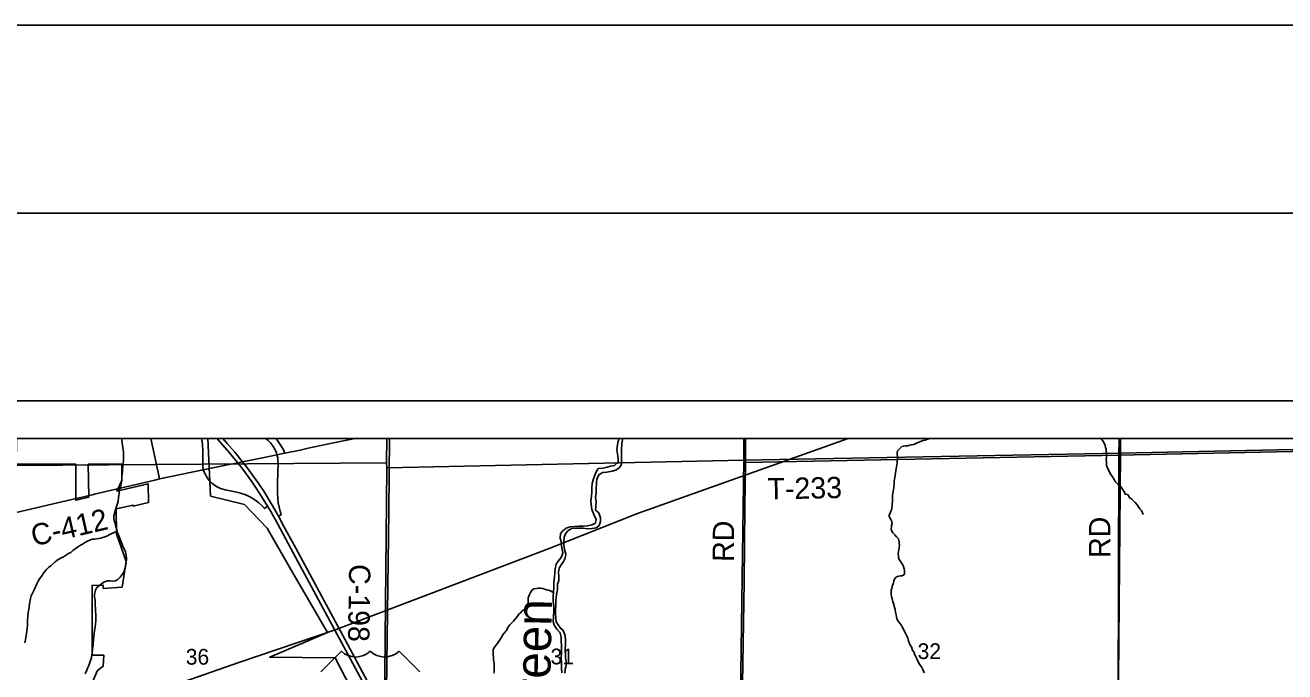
# Model space of a CAD drawing. Extents: x 0 to 34, y 0 to 22.
# Drawn here: x 25.144 to 28.499, y 20.279 to 22 of the extents above; entities that cross this region are included whole.
import ezdxf

# ---------------------------------------------------------------- set-up
doc = ezdxf.new("R2010")
doc.units = 0
for name, color, linetype in [('GM_X_City_Street', 7, 'Continuous'), ('GM_X_County_Road', 7, 'Continuous'), ('GM_X_County_Road_Text', 7, 'Continuous'), ('GM_X_Interchange_Ramps', 7, 'Continuous'), ('GM_X_Minor_River', 7, 'Continuous'), ('GM_X_Minor_River_Text', 7, 'Continuous'), ('GM_X_Rail_Line', 7, 'Continuous'), ('GM_X_Section', 7, 'Continuous'), ('GM_X_Section_Text', 7, 'Continuous'), ('GM_X_State_Route', 7, 'Continuous'), ('GM_X_Township_Road', 7, 'Continuous'), ('GM_X_Township_Road_Text', 7, 'Continuous'), ('GM_X_US_Route', 7, 'Continuous'), ('GM_X_US_Shield', 7, 'Continuous'), ('SH_Border', 7, 'Continuous'), ('SH_Cut_Line', 7, 'Continuous'), ('SH_Data', 7, 'Continuous')]:
    doc.layers.add(name, color=color, linetype=linetype)

msp = doc.modelspace()

# ---------------------------------------------------------------- linework, layer by layer
at = {"layer": 'GM_X_City_Street'}
for points in [[(26.0952, 20.0736), (25.9699, 20.3158), (25.7956, 20.3177), (25.9492, 20.3836), (25.8479, 20.5576), (25.7889, 20.661), (25.7281, 20.7242), (25.638, 20.7466), (25.6303, 20.9), (25.1147, 20.9)], [(25.5023, 20.7921), (25.4882, 20.8587), (25.4785, 20.9)], [(25.113, 20.8313), (25.279, 20.8313), (25.2789, 20.7356), (25.3135, 20.7434), (25.3119, 20.8313), (25.4015, 20.8314), (25.4014, 20.7881), (25.3884, 20.7601), (25.4717, 20.7796), (25.4728, 20.7296), (25.4315, 20.7201), (25.4315, 20.7227), (25.3866, 20.7123), (25.3878, 20.646), (25.4131, 20.5726), (25.4023, 20.5042), (25.3522, 20.5007), (25.3522, 20.5093), (25.3225, 20.5087), (25.3225, 20.3236), (25.3537, 20.3233), (25.3521, 20.2935), (25.3368, 20.282), (25.3235, 20.252)]]:
    msp.add_lwpolyline(points, dxfattribs=at)
at = {"layer": 'GM_X_County_Road'}
for points in [[(26.1076, 20.2958), (26.1077, 20.3027), (26.1124, 20.7064), (26.1147, 20.9)], [(25.4897, 20.7892), (25.5023, 20.7921), (25.6186, 20.8161)], [(25.3323, 20.7524), (25.3905, 20.766), (25.4013, 20.7686)], [(25.4013, 20.7686), (25.478, 20.7865), (25.4897, 20.7892)], [(24.9673, 20.6671), (25.2835, 20.741), (25.2924, 20.7431)], [(25.2924, 20.7431), (25.3224, 20.7501), (25.3323, 20.7524)], [(26.301, 19.8288), (26.3002, 19.8371), (26.2987, 19.8445), (26.2969, 19.8503), (26.2927, 19.8612), (26.2875, 19.8718), (26.2782, 19.8896), (26.2651, 19.9141), (26.25, 19.9419), (26.2307, 19.9774), (26.2049, 20.0253), (26.1749, 20.0809), (26.146, 20.1344), (26.121, 20.1805), (26.1119, 20.1994), (26.1076, 20.2154), (26.1067, 20.2326), (26.1076, 20.2958)]]:
    msp.add_lwpolyline(points, dxfattribs=at)
at = {"layer": 'GM_X_Interchange_Ramps'}
for points in [[(25.8143, 20.8561), (25.8132, 20.8617), (25.8087, 20.8714), (25.803, 20.8809), (25.7978, 20.8881), (25.7918, 20.8945), (25.7851, 20.9)], [(25.819, 20.693), (25.8264, 20.697), (25.8235, 20.7068), (25.8207, 20.717), (25.8182, 20.7287), (25.8168, 20.7397), (25.8161, 20.7553), (25.8165, 20.7789), (25.8173, 20.8124), (25.8176, 20.8303), (25.8175, 20.8426), (25.8167, 20.8485), (25.8143, 20.8561)], [(25.6186, 20.8161), (25.6204, 20.8122), (25.6243, 20.8039), (25.6288, 20.7956), (25.6345, 20.7878), (25.6359, 20.7863)], [(25.6359, 20.7863), (25.6409, 20.7812), (25.648, 20.7753), (25.6557, 20.7708), (25.6642, 20.767), (25.6769, 20.7636), (25.7032, 20.7578), (25.7178, 20.7543), (25.729, 20.7506), (25.7392, 20.7462), (25.7503, 20.7401), (25.7594, 20.734), (25.7667, 20.7285), (25.7742, 20.7216), (25.7814, 20.714), (25.7899, 20.7195)]]:
    msp.add_lwpolyline(points, dxfattribs=at)
at = {"layer": 'GM_X_Minor_River'}
for points in [[(25.4008, 20.9), (25.4014, 20.8945), (25.4021, 20.8888), (25.4036, 20.882), (25.4046, 20.8744), (25.4057, 20.8653), (25.4064, 20.8596), (25.4063, 20.8516), (25.4058, 20.8417), (25.4053, 20.836), (25.4041, 20.8258), (25.4032, 20.8175), (25.4032, 20.8122), (25.4023, 20.8042), (25.4019, 20.7989), (25.4014, 20.7928), (25.401, 20.7856), (25.3993, 20.7754), (25.3981, 20.7693), (25.3958, 20.7633), (25.3945, 20.7549), (25.3937, 20.7485), (25.3929, 20.7432)], [(26.6316, 20.6613), (26.641, 20.6596), (26.6543, 20.6607), (26.6646, 20.6623), (26.6731, 20.6685), (26.6764, 20.6791), (26.6767, 20.6886), (26.6717, 20.7016), (26.6636, 20.7094), (26.6643, 20.7193), (26.665, 20.7329), (26.663, 20.7432), (26.6645, 20.7557), (26.6651, 20.766), (26.6659, 20.7815), (26.667, 20.7925), (26.673, 20.8041), (26.6823, 20.8095), (26.6933, 20.8104), (26.7078, 20.813), (26.7169, 20.8158), (26.7266, 20.822), (26.7321, 20.8306), (26.732, 20.842), (26.7328, 20.8575), (26.7328, 20.8693), (26.7332, 20.886), (26.7354, 20.8969), (26.7363, 20.9)], [(26.7261, 20.9), (26.7239, 20.8931), (26.7214, 20.8829), (26.7199, 20.87), (26.7219, 20.8593), (26.7231, 20.8464), (26.7232, 20.8365), (26.7142, 20.8277), (26.7032, 20.8264), (26.694, 20.8237), (26.6826, 20.8213), (26.6704, 20.8197), (26.6652, 20.8112), (26.6616, 20.8021), (26.6567, 20.7901), (26.6545, 20.7799), (26.6531, 20.7693), (26.6536, 20.7579), (26.6521, 20.7462), (26.651, 20.7341), (26.6515, 20.7246), (26.653, 20.7112), (26.6566, 20.7024)], [(27.5537, 20.9), (27.5509, 20.8992), (27.5455, 20.8969), (27.541, 20.8955), (27.536, 20.8944), (27.5284, 20.8918), (27.52, 20.8881), (27.5109, 20.884), (27.5048, 20.8826), (27.4991, 20.8819), (27.4949, 20.8808), (27.4892, 20.8801), (27.4843, 20.8798), (27.4793, 20.8783), (27.4736, 20.8734), (27.4678, 20.8667)], [(28.0092, 20.9), (28.0099, 20.8992), (28.014, 20.8934), (28.017, 20.8892), (28.0203, 20.8812), (28.0217, 20.8759), (28.0228, 20.8713), (28.0235, 20.8671), (28.0242, 20.8618), (28.0241, 20.8508), (28.0236, 20.8432), (28.024, 20.8383), (28.0239, 20.833), (28.0242, 20.8284), (28.0272, 20.8216), (28.0298, 20.8158), (28.032, 20.8109), (28.0346, 20.8048), (28.0406, 20.7967), (28.0435, 20.7914), (28.0484, 20.7849), (28.0544, 20.778), (28.0604, 20.7741), (28.0653, 20.768), (28.0724, 20.7569), (28.0738, 20.7516), (28.0799, 20.7504), (28.0836, 20.7462), (28.0858, 20.742), (28.0904, 20.7396), (28.096, 20.7343), (28.1005, 20.7293), (28.1065, 20.722), (28.1106, 20.7166), (28.1139, 20.7121), (28.1169, 20.7078), (28.1214, 20.6979)], [(27.4678, 20.8667), (27.4666, 20.8621), (27.4669, 20.8576), (27.4676, 20.853), (27.4672, 20.8454), (27.4667, 20.8397), (27.4663, 20.8352), (27.4647, 20.8246), (27.4642, 20.8189), (27.4634, 20.8147), (27.4618, 20.8075), (27.461, 20.8018), (27.4597, 20.792), (27.4585, 20.7851), (27.4588, 20.7768), (27.458, 20.7719), (27.4576, 20.7677), (27.4563, 20.7609), (27.4551, 20.7548), (27.4543, 20.7491), (27.4539, 20.7419), (27.4538, 20.7336), (27.4533, 20.7241), (27.4528, 20.7157), (27.452, 20.7116), (27.45, 20.7063), (27.4477, 20.7014), (27.445, 20.6965), (27.4449, 20.6923), (27.4487, 20.6858), (27.452, 20.6793), (27.4531, 20.6736), (27.4519, 20.6687), (27.4515, 20.6645), (27.451, 20.6596), (27.4517, 20.6554), (27.4547, 20.6485), (27.4607, 20.6435), (27.4652, 20.6385), (27.4701, 20.6324), (27.4715, 20.6259), (27.4722, 20.6202), (27.4725, 20.6161), (27.4717, 20.6089), (27.4709, 20.6043), (27.4701, 20.599), (27.4696, 20.5926), (27.4699, 20.5865), (27.4702, 20.5815), (27.4747, 20.5743), (27.4784, 20.5689), (27.4825, 20.5617), (27.4855, 20.5529), (27.4865, 20.5476), (27.4865, 20.5434), (27.4861, 20.5385), (27.4796, 20.5347), (27.4754, 20.534), (27.4712, 20.5337), (27.4666, 20.5326), (27.4624, 20.5292), (27.4597, 20.5251), (27.4578, 20.5209), (27.4566, 20.516), (27.4531, 20.5062), (27.4523, 20.5016), (27.4503, 20.4963), (27.4505, 20.4846), (27.4516, 20.4789), (27.4531, 20.4728), (27.4553, 20.4659), (27.4567, 20.461), (27.4585, 20.4545), (27.4596, 20.4499), (27.4611, 20.445), (27.4625, 20.4374), (27.464, 20.4305), (27.465, 20.4252), (27.4661, 20.4206), (27.4683, 20.4149), (27.4724, 20.4096), (27.4769, 20.4042), (27.4803, 20.3985), (27.484, 20.3908), (27.4862, 20.3862), (27.4888, 20.382), (27.4914, 20.3763), (27.4947, 20.3687), (27.4962, 20.3645), (27.498, 20.3584), (27.4999, 20.3519), (27.5055, 20.3439), (27.5065, 20.3374), (27.511, 20.3321), (27.5129, 20.3271), (27.5162, 20.3187), (27.5188, 20.313), (27.5247, 20.3016), (27.5277, 20.2966), (27.531, 20.292), (27.5351, 20.2851)], [(25.3929, 20.7432), (25.3916, 20.7326), (25.3896, 20.7246), (25.3857, 20.7136), (25.3825, 20.7), (25.3802, 20.694), (25.3801, 20.6875), (25.3816, 20.6818), (25.383, 20.6761), (25.3848, 20.6689), (25.3867, 20.6628), (25.3881, 20.6567), (25.3903, 20.6487), (25.3936, 20.6407), (25.3969, 20.6315), (25.3995, 20.6247), (25.4025, 20.6186), (25.4047, 20.6121), (25.4091, 20.6048), (25.411, 20.598), (25.4135, 20.5884), (25.4142, 20.5812), (25.4133, 20.5683), (25.4117, 20.5611), (25.4089, 20.5505), (25.4066, 20.5441), (25.4038, 20.5388), (25.3973, 20.5305), (25.3908, 20.5242), (25.3847, 20.5208), (25.3763, 20.5205), (25.3706, 20.5213), (25.3634, 20.5207), (25.3554, 20.5181), (25.3486, 20.514), (25.3424, 20.5087), (25.3352, 20.5035), (25.3313, 20.4959), (25.3297, 20.4895), (25.3285, 20.4838), (25.3292, 20.4774), (25.3302, 20.4701), (25.3305, 20.4633), (25.3305, 20.458), (25.3315, 20.4454), (25.3318, 20.4382), (25.3325, 20.4325), (25.3328, 20.4253), (25.3326, 20.4154), (25.3318, 20.4063), (25.3305, 20.398), (25.3289, 20.3889), (25.3277, 20.3802), (25.3269, 20.3738), (25.326, 20.365), (25.3251, 20.3521), (25.3234, 20.337), (25.3229, 20.3298), (25.3217, 20.3233), (25.3205, 20.3173), (25.3189, 20.3112), (25.3162, 20.3033), (25.3138, 20.2957), (25.3115, 20.2904), (25.308, 20.2832), (25.3037, 20.2734)], [(26.6566, 20.7024), (26.6602, 20.6936), (26.6649, 20.6851), (26.6631, 20.6749), (26.6534, 20.6698), (26.6416, 20.6675), (26.6306, 20.6663), (26.6196, 20.6662), (26.6078, 20.6654), (26.5957, 20.665), (26.5853, 20.6615), (26.576, 20.6541), (26.5701, 20.6467), (26.5691, 20.635), (26.5715, 20.6254), (26.5727, 20.6144), (26.5747, 20.6044), (26.5763, 20.5949), (26.5718, 20.5829), (26.5636, 20.5736), (26.5581, 20.565), (26.5559, 20.5533), (26.5548, 20.5435), (26.5541, 20.5309), (26.5526, 20.5173), (26.5519, 20.5044), (26.5511, 20.4912), (26.5505, 20.4794), (26.5505, 20.4661), (26.552, 20.4524), (26.552, 20.4399), (26.5509, 20.4255), (26.5502, 20.413), (26.5533, 20.403), (26.5599, 20.3922), (26.5687, 20.3825), (26.5718, 20.3706), (26.5719, 20.36), (26.5723, 20.3489), (26.5725, 20.3394), (26.5722, 20.3292), (26.5718, 20.3159), (26.5722, 20.303), (26.573, 20.2893), (26.5734, 20.2764)], [(25.3894, 20.6516), (25.3835, 20.6506), (25.3766, 20.6477), (25.3679, 20.6432), (25.3621, 20.6399), (25.3564, 20.6384), (25.3454, 20.6347), (25.3401, 20.634), (25.3287, 20.6323), (25.3222, 20.6316), (25.3119, 20.6279), (25.3047, 20.6242), (25.2966, 20.6189), (25.2913, 20.6156), (25.2833, 20.6103), (25.271, 20.6014), (25.2657, 20.5965), (25.2599, 20.5935), (25.2515, 20.5883), (25.2462, 20.5845), (25.2401, 20.5823), (25.2298, 20.576), (25.2229, 20.5711), (25.2122, 20.5614), (25.2064, 20.5561), (25.201, 20.5516), (25.1964, 20.546), (25.1918, 20.5407), (25.1891, 20.5354), (25.1825, 20.5264), (25.1787, 20.5203), (25.1756, 20.5132), (25.1686, 20.4973), (25.1639, 20.4882), (25.1604, 20.4807), (25.1581, 20.4743), (25.156, 20.4602), (25.1552, 20.453), (25.1539, 20.4443), (25.1523, 20.4367), (25.1514, 20.4265), (25.1502, 20.4163), (25.15, 20.4011), (25.1496, 20.395), (25.1479, 20.3798), (25.1463, 20.3707), (25.1454, 20.3639), (25.1434, 20.3556)], [(26.5817, 20.2754), (26.582, 20.286), (26.5849, 20.2958), (26.5848, 20.3061), (26.5832, 20.3171), (26.5835, 20.3281), (26.5827, 20.3399), (26.583, 20.3509), (26.5837, 20.3619), (26.5822, 20.3756), (26.5772, 20.3891), (26.5698, 20.395), (26.5636, 20.4035), (26.5581, 20.412), (26.5576, 20.4219), (26.5564, 20.4337), (26.5564, 20.4451), (26.5574, 20.4557), (26.5573, 20.4671), (26.558, 20.4784), (26.5598, 20.4883), (26.5616, 20.4985), (26.5623, 20.5125), (26.5653, 20.5223), (26.5656, 20.5329), (26.5647, 20.5439), (26.5665, 20.5549), (26.5713, 20.5635), (26.5776, 20.5728), (26.582, 20.5814), (26.5842, 20.5924), (26.5804, 20.6043), (26.5788, 20.6165), (26.5787, 20.6263), (26.5798, 20.6373), (26.5834, 20.6463), (26.5905, 20.6553), (26.5997, 20.6603), (26.6103, 20.6608), (26.6202, 20.6609), (26.6316, 20.6613)], [(26.5511, 20.49), (26.5489, 20.4905), (26.5448, 20.4936), (26.5376, 20.4959), (26.5327, 20.4971), (26.5274, 20.4987), (26.5229, 20.501), (26.5156, 20.5015), (26.5103, 20.5011), (26.5058, 20.5008), (26.4989, 20.4997), (26.4936, 20.4956), (26.4901, 20.4896), (26.487, 20.4843), (26.4854, 20.4801), (26.4839, 20.4752), (26.4838, 20.4695), (26.4841, 20.4619), (26.4825, 20.4551), (26.4783, 20.4491), (26.4748, 20.4446), (26.4679, 20.4409), (26.4637, 20.4356), (26.4591, 20.4322), (26.4564, 20.4277), (26.4495, 20.4194), (26.4452, 20.4141), (26.4349, 20.404), (26.431, 20.3984), (26.4275, 20.3923), (26.4248, 20.3878), (26.4194, 20.381), (26.4152, 20.3765), (26.4133, 20.3724), (26.4102, 20.3667), (26.4051, 20.3588), (26.4009, 20.3531), (26.3967, 20.3479), (26.3928, 20.3422), (26.3909, 20.3373), (26.3904, 20.3312), (26.3907, 20.3259), (26.3914, 20.3164), (26.3917, 20.3122), (26.3924, 20.3065), (26.3931, 20.3004), (26.3929, 20.2807), (26.3924, 20.275)], [(27.5351, 20.2851), (27.5366, 20.2809), (27.5396, 20.276)]]:
    msp.add_lwpolyline(points, dxfattribs=at)
at = {"layer": 'GM_X_Rail_Line'}
msp.add_lwpolyline([(24.6857, 19.9193), (25.3089, 20.1629), (25.713, 20.3036), (25.9724, 20.3916), (26.54, 20.6067), (26.7751, 20.7), (27.3361, 20.9)], dxfattribs=at)
at = {"layer": 'GM_X_Section'}
for points in [[(26.1071, 20.9), (25.1211, 20.9), (25.1198, 20.8277), (26.1064, 20.8349)], [(27.0585, 20.9), (26.1071, 20.9), (26.1064, 20.8349), (26.1071, 20.822), (27.0582, 20.8419)], [(28.0617, 20.9), (27.0585, 20.9), (27.0582, 20.8419), (28.0611, 20.8611)], [(29.0649, 20.9), (28.0617, 20.9), (28.0611, 20.8611), (29.0645, 20.8822)], [(29.0645, 20.8822), (29.0488, 19.8748), (29.0105, 19.8743), (28.0523, 19.8602), (28.0611, 20.8611)], [(26.1064, 20.8349), (26.1071, 20.822), (26.0975, 19.8234), (25.0925, 19.8455), (25.1198, 20.8277)], [(27.0582, 20.8419), (27.044, 19.8365), (27.0095, 19.8363), (26.0975, 19.8234), (26.1071, 20.822)], [(28.0611, 20.8611), (28.0523, 19.8602), (28.0159, 19.8585), (27.044, 19.8365), (27.0582, 20.8419)]]:
    msp.add_lwpolyline(points, close=True, dxfattribs=at)
at = {"layer": 'GM_X_State_Route'}
for p, q in [((25.7804, 20.8493), (25.8143, 20.8561)), ((25.8143, 20.8561), (25.835, 20.8605)), ((25.6186, 20.8161), (25.6833, 20.8295))]:
    msp.add_line(p, q, dxfattribs=at)
for points in [[(25.6135, 20.9), (25.6136, 20.8997), (25.6147, 20.8943)], [(25.819, 20.693), (25.8084, 20.7118), (25.7996, 20.7265), (25.7794, 20.7593), (25.7662, 20.779), (25.7547, 20.7955), (25.7333, 20.8247), (25.7234, 20.8377), (25.7024, 20.8633), (25.6822, 20.887), (25.6705, 20.9)], [(25.8762, 20.8692), (25.8978, 20.8738), (25.9655, 20.888), (26.0231, 20.9)], [(25.6147, 20.8943), (25.6163, 20.8861), (25.6173, 20.8666), (25.6171, 20.8436), (25.6171, 20.8266), (25.6186, 20.8161)], [(25.835, 20.8605), (25.836, 20.8607), (25.8762, 20.8692)], [(25.6833, 20.8295), (25.7107, 20.8352), (25.7234, 20.8377), (25.7804, 20.8493)], [(26.2857, 19.8286), (26.2786, 19.8411), (26.2659, 19.8648), (26.1166, 20.142), (26.1018, 20.1688), (26.0817, 20.2061), (26.049, 20.2665), (25.9769, 20.4002), (25.8649, 20.6078), (25.8325, 20.6678), (25.819, 20.693)]]:
    msp.add_lwpolyline(points, dxfattribs=at)
at = {"layer": 'GM_X_Township_Road'}
for p, q in [((28.0568, 20.8556), (28.0576, 20.9)), ((27.0623, 20.8364), (28.0568, 20.8556)), ((28.0544, 19.8539), (28.0568, 20.8556)), ((28.0568, 20.8556), (28.5606, 20.8662))]:
    msp.add_line(p, q, dxfattribs=at)
for points in [[(25.836, 20.8607), (25.8318, 20.8698), (25.8248, 20.8814), (25.8163, 20.8948), (25.812, 20.9)], [(27.0492, 19.834), (27.0521, 20.0929), (27.0558, 20.3), (27.0587, 20.5188), (27.0611, 20.719), (27.0623, 20.8364), (27.0625, 20.9)]]:
    msp.add_lwpolyline(points, dxfattribs=at)
at = {"layer": 'GM_X_US_Route'}
for points in [[(25.6545, 20.9), (25.6575, 20.8969), (25.6829, 20.8679), (25.7107, 20.8352)], [(25.6705, 20.9), (25.6822, 20.887), (25.7024, 20.8633), (25.7234, 20.8377), (25.7333, 20.8247), (25.7547, 20.7955), (25.7662, 20.779), (25.7794, 20.7593), (25.7996, 20.7265), (25.8084, 20.7118), (25.819, 20.693)], [(25.7107, 20.8352), (25.7255, 20.8153), (25.7472, 20.7859), (25.7576, 20.7705), (25.7695, 20.7524), (25.7899, 20.7195), (25.7985, 20.7052), (25.8082, 20.6879), (25.8097, 20.6852)], [(25.8097, 20.6852), (25.823, 20.6607), (25.8518, 20.6071), (26.072, 20.1992), (26.1019, 20.1434), (26.1058, 20.1362), (26.1444, 20.0646)], [(25.819, 20.693), (25.8325, 20.6678), (25.8649, 20.6078), (25.9769, 20.4002), (26.049, 20.2665), (26.0817, 20.2061), (26.1018, 20.1688), (26.1166, 20.142), (26.2659, 19.8648), (26.2786, 19.8411), (26.2857, 19.8286)]]:
    msp.add_lwpolyline(points, dxfattribs=at)
at = {"layer": 'GM_X_US_Shield'}
for p, q in [((25.9863, 20.3338), (25.9314, 20.2789)), ((26.195, 20.2789), (26.1401, 20.3338))]:
    msp.add_line(p, q, dxfattribs=at)
for centre in [(26.0247, 20.3731), (26.1016, 20.3731)]:
    msp.add_arc(centre, 0.0549, 225.573, 314.427, dxfattribs=at)
at = {"layer": 'SH_Border'}
msp.add_lwpolyline([(1.5, 21.5), (33.5, 21.5), (33.5, 0.5), (1.5, 0.5)], close=True, dxfattribs=at)
at = {"layer": 'SH_Cut_Line'}
msp.add_lwpolyline([(0, 0), (34, 0), (34, 22), (0, 22)], close=True, dxfattribs=at)
at = {"layer": 'SH_Data'}
for points in [[(23.4167, 21), (30.4167, 21), (30.4167, 14), (23.4167, 14)], [(23.5167, 20.9), (30.3167, 20.9), (30.3167, 14.1), (23.5167, 14.1)]]:
    msp.add_lwpolyline(points, close=True, dxfattribs=at)

# ---------------------------------------------------------------- texts
at = {"layer": 'GM_X_County_Road_Text'}
for s, rotation, p in [('C-412', 13.0365, (25.1671, 20.6125)), ('C-198', 269.1731, (26.007, 20.5659))]:
    msp.add_text(s, height=0.05682, rotation=rotation, dxfattribs=at).set_placement(p)
at = {"layer": 'GM_X_Minor_River_Text'}
msp.add_text('Green', height=0.09475, rotation=88.8302, dxfattribs=at).set_placement((26.54, 20.1191))
at = {"layer": 'GM_X_Section_Text'}
for s, p in [('36', (25.5719, 20.2979)), ('31', (26.5436, 20.2987)), ('32', (27.5211, 20.3129))]:
    msp.add_text(s, height=0.04186, rotation=0, dxfattribs=at).set_placement(p)
at = {"layer": 'GM_X_Township_Road_Text'}
for s, rotation, p in [('T-233', 1.1237, (27.1218, 20.7375)), ('RD', 89.5063, (27.0317, 20.5713)), ('RD', 90, (28.0342, 20.582))]:
    msp.add_text(s, height=0.05682, rotation=rotation, dxfattribs=at).set_placement(p)

doc.saveas('drawing.dxf')
